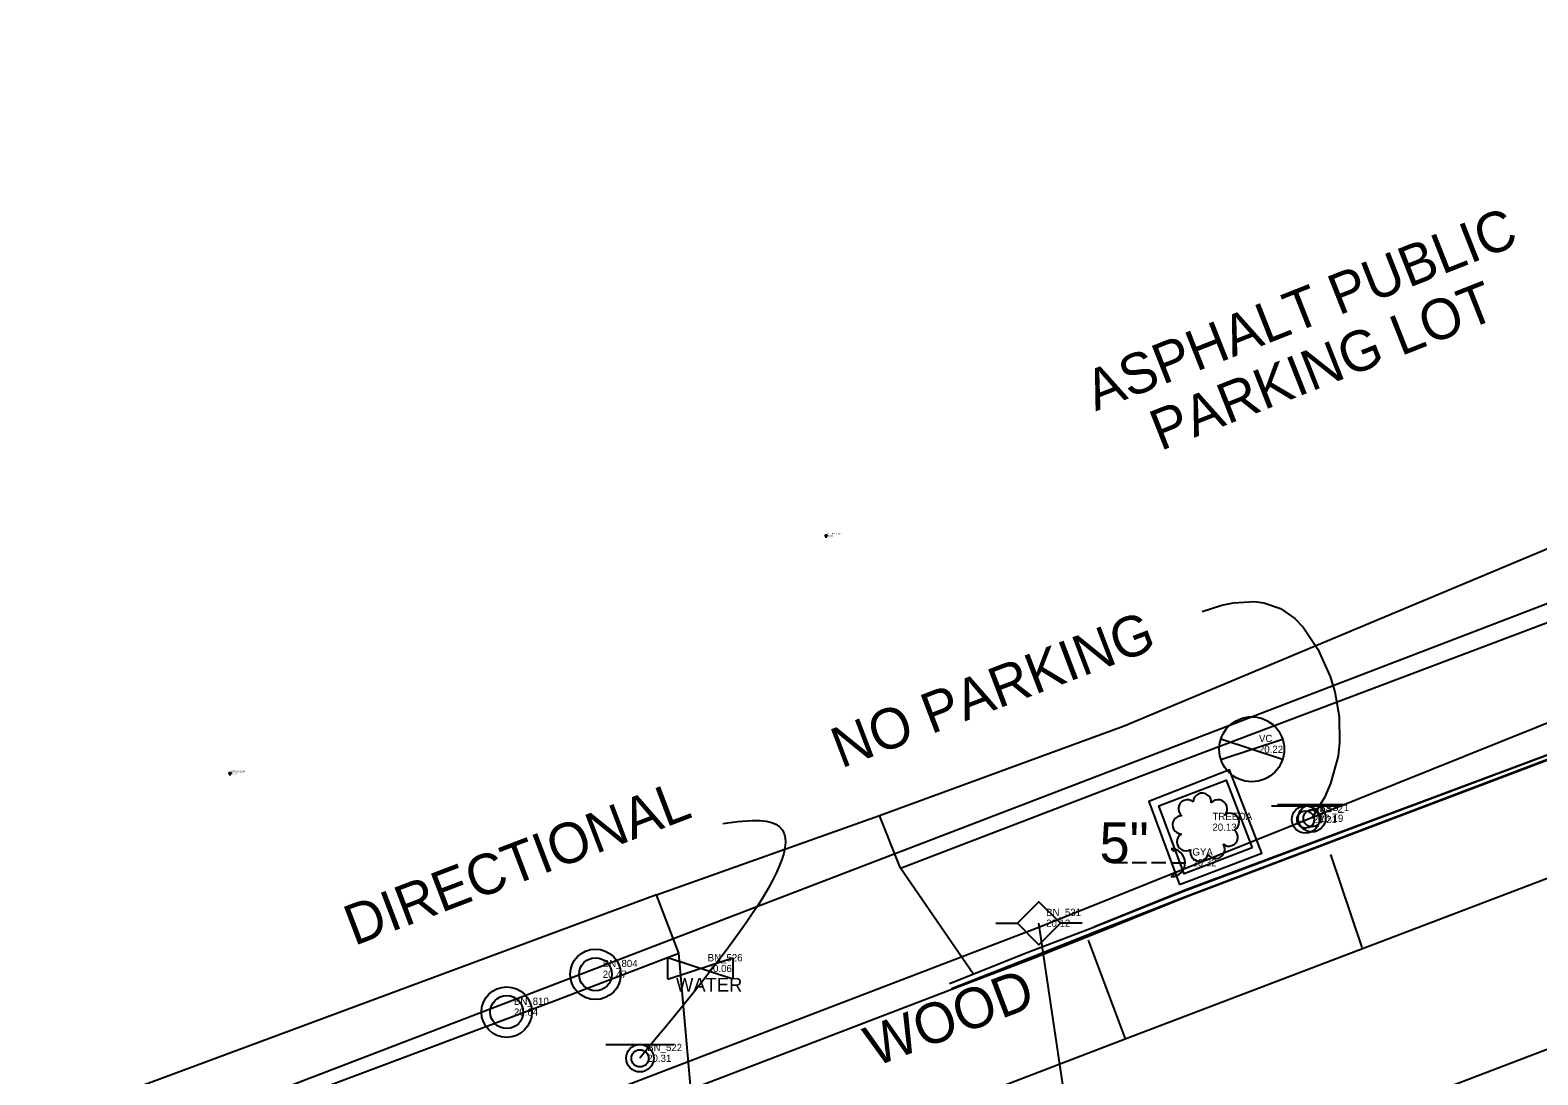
# Model space of a CAD drawing. Extents: x 509744 to 512285, y 1314862 to 1316822.
# Drawn here: x 510235.3 to 510339.7, y 1315368.4 to 1315440.8 of the extents above; entities that cross this region are included whole.
import ezdxf

# ---------------------------------------------------------------- set-up
doc = ezdxf.new("R2010")
doc.units = 0
for name, color, linetype in [('Bollard_ep', 7, 'Continuous'), ('CGBack_ep', 7, 'Continuous'), ('CGFace_ep', 7, 'Continuous'), ('Driveway_ep', 7, 'Continuous'), ('ElecAer_ep', 7, 'Continuous'), ('GroundShot_ep', 7, 'Continuous'), ('GuyWireAnchor_ep', 7, 'Continuous'), ('LaneLine_ep', 7, 'Continuous'), ('PavtAsphalt_ep', 7, 'Continuous'), ('PavtBreak_ep', 7, 'Continuous'), ('PMRK_ep', 7, 'Continuous'), ('PoleElec_ep', 7, 'Continuous'), ('RWLine_ep', 7, 'Continuous'), ('SidewalkBack_ep', 7, 'Continuous'), ('SidewalkFront_ep', 7, 'Continuous'), ('SignSingle_ep', 7, 'Continuous'), ('TextElevLabel', 7, 'Continuous'), ('TextPtLabel', 7, 'Continuous'), ('TextTopoLabel_ep', 7, 'Continuous'), ('TextUtilLabel_ep', 7, 'Continuous'), ('TreeOak_ep', 7, 'Continuous'), ('ValveCover_ep', 7, 'Continuous'), ('ValveWater_ep', 7, 'Continuous')]:
    doc.layers.add(name, color=color, linetype=linetype)

msp = doc.modelspace()

# ---------------------------------------------------------------- linework, layer by layer
at = {"layer": 'Bollard_ep'}
for centre, radius in [((510274.47, 1315375.41), 1.75), ((510274.47, 1315375.41), 1.75), ((510274.47, 1315375.41), 1.14), ((510268.32, 1315372.79), 1.75), ((510268.32, 1315372.79), 1.75), ((510268.32, 1315372.79), 1.14)]:
    msp.add_circle(centre, radius, dxfattribs=at)
at = {"layer": 'CGBack_ep'}
for points in [[(510315.26, 1315381.2), (510352.61, 1315395.19), (510359.59, 1315397.91), (510362.04, 1315398.86)], [(510298.98, 1315374.78), (510304.36, 1315376.93), (510309.04, 1315378.69), (510315.26, 1315381.2)]]:
    msp.add_lwpolyline(points, dxfattribs=at)
msp.add_lwpolyline([(510314.91, 1315381.64), (510320.62, 1315383.81), (510318.39, 1315389.58), (510312.79, 1315387.39)], close=True, dxfattribs=at)
at = {"layer": 'CGFace_ep'}
for points in [[(510315.41, 1315380.83), (510352.7, 1315394.97), (510359.66, 1315397.71), (510362.13, 1315398.64), (510373.18, 1315402.86), (510377.72, 1315404.58), (510408.85, 1315416.45), (510452.53, 1315433.53), (510452.91, 1315433.65)], [(510315.25, 1315381.23), (510352.61, 1315395.19), (510359.56, 1315397.98), (510362.04, 1315398.87)], [(510299.12, 1315374.42), (510304.52, 1315376.54), (510309.16, 1315378.39), (510315.41, 1315380.83)]]:
    msp.add_lwpolyline(points, dxfattribs=at)
msp.add_lwpolyline([(510319.94, 1315384.16), (510315.25, 1315382.38), (510313.48, 1315387.07), (510318.16, 1315388.85)], close=True, dxfattribs=at)
at = {"layer": 'Driveway_ep'}
msp.add_line((510278.7, 1315380.91), (510294.15, 1315386.4), dxfattribs=at)
for points in [[(510311.09, 1315392.62), (510357.52, 1315412.06), (510404.31, 1315429.68)], [(510294.15, 1315386.4), (510311.09, 1315392.62)], [(510300.63, 1315375.44), (510295.6, 1315382.77), (510294.15, 1315386.4)], [(510278.7, 1315380.91), (510231.83, 1315363.52), (510212.56, 1315356.33), (510184.95, 1315346.12), (510138.07, 1315328.73), (510091.2, 1315311.33), (510077.98, 1315306.43), (510079.78, 1315300.26)], [(510281.07, 1315367.45), (510280.24, 1315376.87), (510278.7, 1315380.91)]]:
    msp.add_lwpolyline(points, dxfattribs=at)
at = {"layer": 'ElecAer_ep'}
for p, q in [((510305.3, 1315378.72), (510380.45, 1315408.93)), ((510316.02, 1315305.77), (510305.18, 1315378.95))]:
    msp.add_line(p, q, dxfattribs=at)
msp.add_lwpolyline([(509905.68, 1315225.77), (509981.67, 1315254.87), (510039.68, 1315277.12), (510060.9, 1315285.03), (510142.68, 1315316.01), (510220.69, 1315346.3), (510305.3, 1315378.72)], dxfattribs=at)
at = {"layer": 'GroundShot_ep'}
for p, q in [((510290.57, 1315405.79), (510290.32, 1315405.79)), ((510290.45, 1315405.66), (510290.45, 1315405.91)), ((510249.29, 1315389.31), (510249.04, 1315389.31)), ((510249.17, 1315389.18), (510249.17, 1315389.43))]:
    msp.add_line(p, q, dxfattribs=at)
at = {"layer": 'GuyWireAnchor_ep'}
for p, q in [((510314.33, 1315384.11), (510314.53, 1315383.92)), ((510310.31, 1315383.15), (510311.31, 1315383.15)), ((510311.64, 1315383.15), (510312.64, 1315383.15)), ((510312.97, 1315383.15), (510313.97, 1315383.15)), ((510314.31, 1315383.14), (510315.31, 1315383.14)), ((510314.35, 1315382.17), (510314.59, 1315382.4))]:
    msp.add_line(p, q, dxfattribs=at)
msp.add_arc((510314.33, 1315383.14), 0.973, 271.14, 90.0059, dxfattribs=at)
at = {"layer": 'LaneLine_ep'}
msp.add_lwpolyline([(510321.99, 1315363.21), (510368.75, 1315381.05), (510407.51, 1315396.03), (510481.77, 1315424.28), (510512.34, 1315436.08)], dxfattribs=at)
at = {"layer": 'PavtAsphalt_ep'}
msp.add_lwpolyline([(510207.65, 1315339.28), (510244.53, 1315353.42), (510263.66, 1315360.74), (510275.54, 1315365.33), (510277.97, 1315366.15), (510281.07, 1315367.45), (510299.14, 1315374.38), (510304.56, 1315376.44), (510309.2, 1315378.29), (510315.42, 1315380.79), (510352.69, 1315394.92), (510362.13, 1315398.63), (510408.86, 1315416.42), (510452.76, 1315432.95)], dxfattribs=at)
at = {"layer": 'PavtBreak_ep'}
msp.add_line((510284.4, 1315360.71), (510311.16, 1315370.93), dxfattribs=at)
at = {"layer": 'PMRK_ep'}
msp.add_line((510327.58, 1315377.26), (510325.41, 1315383.71), dxfattribs=at)
for points in [[(510311.16, 1315370.93), (510348.46, 1315385.15), (510365.78, 1315391.96), (510386.66, 1315399.86), (510405.8, 1315407.39), (510430.14, 1315416.5), (510452.76, 1315425.13)], [(510308.59, 1315377.78), (510311.16, 1315370.93)]]:
    msp.add_lwpolyline(points, dxfattribs=at)
at = {"layer": 'PoleElec_ep'}
for p, q in [((510302.19, 1315378.95), (510303.69, 1315378.95)), ((510308.17, 1315378.95), (510306.67, 1315378.95))]:
    msp.add_line(p, q, dxfattribs=at)
msp.add_lwpolyline([(510303.69, 1315378.95), (510305.18, 1315380.44), (510306.67, 1315378.95), (510305.18, 1315377.46), (510303.69, 1315378.95)], dxfattribs=at)
at = {"layer": 'RWLine_ep'}
msp.add_line((509788.71, 1315189.47), (510457.4, 1315446.01), dxfattribs=at)
at = {"layer": 'SidewalkBack_ep'}
for points in [[(510295.6, 1315382.77), (510312.26, 1315389.16), (510359.04, 1315406.82), (510405.68, 1315424.87), (510449.83, 1315441.51)], [(510034.18, 1315283.6), (510046.1, 1315288.12), (510069.47, 1315296.3), (510093.03, 1315305.35), (510116.8, 1315313.88), (510139.6, 1315323.57), (510162.98, 1315332.44), (510186.35, 1315341.3), (510209.73, 1315350.17), (510233.1, 1315359.03), (510256.48, 1315367.89), (510271.56, 1315373.54), (510280.24, 1315376.87)]]:
    msp.add_lwpolyline(points, dxfattribs=at)
at = {"layer": 'SidewalkFront_ep'}
msp.add_line((510309.03, 1315378.72), (510315.25, 1315381.23), dxfattribs=at)
at = {"layer": 'SignSingle_ep'}
for p, q in [((510321.28, 1315387.08), (510326.03, 1315387.08)), ((510321.71, 1315387.17), (510326.46, 1315387.17)), ((510275.18, 1315370.54), (510279.93, 1315370.54))]:
    msp.add_line(p, q, dxfattribs=at)
for centre, radius in [((510323.65, 1315386.13), 0.95), ((510323.65, 1315386.13), 0.594), ((510324.09, 1315386.22), 0.95), ((510324.09, 1315386.22), 0.594), ((510277.55, 1315369.59), 0.95), ((510277.55, 1315369.59), 0.594)]:
    msp.add_circle(centre, radius, dxfattribs=at)
at = {"layer": 'TextTopoLabel_ep'}
msp.add_lwpolyline([(510316.48, 1315400.55), (510317.84, 1315400.98), (510318.66, 1315401.15), (510320.11, 1315401.23), (510320.76, 1315401.15), (510321.91, 1315400.76), (510322.9, 1315400.07), (510323.48, 1315399.47), (510324.5, 1315397.94), (510325.35, 1315396.04), (510325.67, 1315394.98), (510325.98, 1315393.27), (510326.01, 1315391.46), (510325.9, 1315390.52), (510325.38, 1315388.62), (510324.96, 1315387.65), (510324.09, 1315386.22)], dxfattribs=at)
msp.add_spline([(510283.3, 1315385.86), (510285.85, 1315386.07), (510277.55, 1315369.59)], degree=3, dxfattribs=at)
at = {"layer": 'TreeOak_ep'}
for centre, radius, start, end in [((510315.46, 1315386.88), 0.624, 50.7185, 233.084), ((510316.49, 1315387.33), 0.629, 355.3943, 176.6549), ((510317.6, 1315386.88), 0.627, 315.0898, 140.6833), ((510315.06, 1315385.76), 0.625, 87.3095, 269.5618), ((510318.42, 1315385.94), 0.626, 299.4354, 127.2613), ((510315.36, 1315384.59), 0.626, 119.4469, 301.0197), ((510318.34, 1315384.91), 0.623, 229.2872, 51.2025), ((510317.43, 1315384.06), 0.628, 211.1877, 36.8199), ((510316.29, 1315383.88), 0.625, 164.2871, 346.2767)]:
    msp.add_arc(centre, radius, start, end, dxfattribs=at)
at = {"layer": 'ValveCover_ep'}
for p, q in [((510317.78, 1315390.29), (510322.05, 1315391.71)), ((510322.05, 1315390.29), (510317.78, 1315391.71))]:
    msp.add_line(p, q, dxfattribs=at)
msp.add_circle((510319.92, 1315391), 2.25, dxfattribs=at)
at = {"layer": 'ValveWater_ep'}
for p, q in [((510283.99, 1315375.06), (510279.49, 1315376.56)), ((510279.49, 1315375.06), (510283.99, 1315376.56)), ((510279.49, 1315375.06), (510279.49, 1315376.56)), ((510283.99, 1315376.56), (510283.99, 1315375.06))]:
    msp.add_line(p, q, dxfattribs=at)

# ---------------------------------------------------------------- texts
at = {"layer": 'TextElevLabel'}
for s, height, p in [('20.80', 0.1, (510290.55, 1315405.74)), ('20.22', 0.5, (510320.42, 1315390.75)), ('20.61', 0.1, (510249.27, 1315389.26)), ('20.21', 0.5, (510324.15, 1315385.88)), ('20.19', 0.5, (510324.59, 1315385.97)), ('20.13', 0.5, (510317.2, 1315385.35)), ('20.32', 0.5, (510315.81, 1315382.89)), ('20.12', 0.5, (510305.68, 1315378.7)), ('20.06', 0.5, (510282.24, 1315375.56)), ('20.47', 0.5, (510274.97, 1315375.16)), ('20.64', 0.5, (510268.82, 1315372.54)), ('20.31', 0.5, (510278.05, 1315369.34))]:
    msp.add_text(s, height=height, dxfattribs=at).set_placement(p)
at = {"layer": 'TextPtLabel'}
for s, height, p in [('DEFAULT_832', 0.1, (510290.55, 1315405.89)), ('VC', 0.5, (510320.42, 1315391.5)), ('DEFAULT_840', 0.1, (510249.27, 1315389.41)), ('SSS_1', 0.5, (510324.59, 1315386.72)), ('TREEOA', 0.5, (510317.2, 1315386.1)), ('SSS_2', 0.5, (510324.15, 1315386.63)), ('GYA', 0.5, (510315.81, 1315383.64)), ('BN_531', 0.5, (510305.68, 1315379.45)), ('BN_526', 0.5, (510282.24, 1315376.31)), ('BN_804', 0.5, (510274.97, 1315375.91)), ('BN_810', 0.5, (510268.82, 1315373.29)), ('BN_522', 0.5, (510278.05, 1315370.09))]:
    msp.add_text(s, height=height, dxfattribs=at).set_placement(p)
at = {"layer": 'TextTopoLabel_ep'}
for s, rotation, p in [('ASPHALT PUBLIC ', 21.5246, (510309.1, 1315414.4)), ('PARKING LOT', 21.5246, (510313.6, 1315411.66)), ('NO PARKING', 20.866, (510291.49, 1315389.66)), ('DIRECTIONAL', 20.866, (510257.76, 1315377.36))]:
    msp.add_text(s, height=2.8, rotation=rotation, dxfattribs=at).set_placement(p)
msp.add_text('5"', height=2.8, dxfattribs=at).set_placement((510309.38, 1315383.13))
at = {"layer": 'TextUtilLabel_ep'}
msp.add_text('WOOD', height=2.8, rotation=20.7738, dxfattribs=at).set_placement((510293.81, 1315368.98))
at = {"layer": 'ValveWater_ep'}
msp.add_text('WATER', height=0.95, dxfattribs=at).set_placement((510280.05, 1315374.21))

doc.saveas('drawing.dxf')
